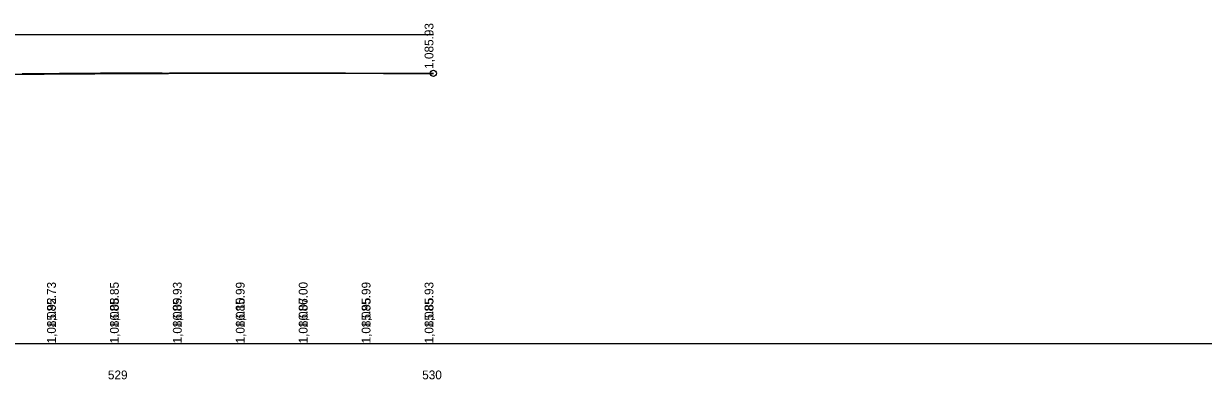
# Model space of a CAD drawing. Extents: x 2241514 to 2245530, y 509521 to 510188.
# Drawn here: x 2243146.9 to 2243521.9, y 509759.6 to 509872.8 of the extents above; entities that cross this region are included whole.
import ezdxf

# ---------------------------------------------------------------- set-up
doc = ezdxf.new("R2010")
doc.units = 0
for name, color, linetype in [('GK_Cells', 7, 'Continuous'), ('PF_P_Grade_Line', 7, 'Continuous'), ('PF_P_Sta_Elev_Text', 7, 'Continuous'), ('PF_P_Text', 7, 'Continuous'), ('PF_X_Ground_Line', 7, 'Continuous'), ('PF_X_Text', 7, 'Continuous')]:
    doc.layers.add(name, color=color, linetype=linetype)

msp = doc.modelspace()

# ---------------------------------------------------------------- linework, layer by layer
at = {"layer": 'GK_Cells'}
msp.add_line((2241529.6, 509771.03), (2245529.6, 509771.03), dxfattribs=at)
at = {"layer": 'PF_P_Grade_Line'}
msp.add_spline([(2242782.14, 509848.05), (2242792.04, 509848.44), (2242801.94, 509848.82), (2242811.84, 509849.19), (2242821.74, 509849.55), (2242831.64, 509849.9), (2242841.54, 509850.25), (2242851.44, 509850.58), (2242861.34, 509850.91), (2242871.24, 509851.23), (2242881.14, 509851.54), (2242891.04, 509851.84), (2242900.94, 509852.13), (2242910.84, 509852.42), (2242920.74, 509852.69), (2242930.64, 509852.96), (2242940.54, 509853.22), (2242950.44, 509853.47), (2242960.34, 509853.71), (2242970.24, 509853.95), (2242980.14, 509854.17), (2242990.04, 509854.39), (2242999.94, 509854.6), (2243009.84, 509854.8), (2243019.74, 509854.99), (2243029.64, 509855.17), (2243039.54, 509855.34), (2243049.44, 509855.51), (2243059.34, 509855.67), (2243069.24, 509855.82), (2243079.14, 509855.96), (2243089.04, 509856.09), (2243098.94, 509856.21), (2243108.84, 509856.32), (2243118.74, 509856.43), (2243128.64, 509856.53), (2243138.54, 509856.62), (2243148.44, 509856.7), (2243158.34, 509856.77), (2243168.24, 509856.83), (2243178.14, 509856.89), (2243188.04, 509856.93), (2243197.94, 509856.97), (2243207.84, 509857), (2243217.74, 509857.02), (2243227.64, 509857.03), (2243237.54, 509857.04), (2243247.44, 509857.03), (2243257.34, 509857.02), (2243267.24, 509857), (2243277.14, 509856.97)], degree=3, dxfattribs=at)
at = {"layer": 'PF_P_Text'}
msp.add_line((2242782.14, 509869.31), (2243277.14, 509869.31), dxfattribs=at)
msp.add_circle((2243277.14, 509856.97), 1, dxfattribs=at)
at = {"layer": 'PF_X_Ground_Line'}
for points in [[(2243146.43, 509856.9), (2243148.27, 509856.92), (2243148.65, 509856.92), (2243150.46, 509856.93), (2243151.49, 509856.93), (2243152.13, 509856.94), (2243152.81, 509856.94), (2243153.65, 509856.94), (2243154.83, 509856.94), (2243155.37, 509856.94), (2243155.95, 509856.94), (2243156.1, 509856.94), (2243157.34, 509856.95), (2243158.25, 509856.96), (2243158.58, 509856.96), (2243159.94, 509856.97), (2243161.41, 509856.98), (2243162.36, 509856.99), (2243163.99, 509857.01), (2243164.85, 509857.02), (2243165.15, 509857.02), (2243165.63, 509857.02), (2243167.05, 509857.04), (2243167.54, 509857.04), (2243168.51, 509857.05), (2243169.13, 509857.05), (2243169.71, 509857.05), (2243171.28, 509857.07), (2243171.32, 509857.07), (2243171.37, 509857.07), (2243172.45, 509857.09), (2243172.54, 509857.09), (2243173.47, 509857.1), (2243173.54, 509857.1), (2243175.21, 509857.11), (2243175.35, 509857.11), (2243175.62, 509857.11), (2243176.15, 509857.11), (2243178.14, 509857.11), (2243179.22, 509857.11), (2243180.12, 509857.11), (2243181.5, 509857.11), (2243181.99, 509857.1), (2243182.37, 509857.1), (2243184.3, 509857.1), (2243184.51, 509857.1), (2243186.28, 509857.09), (2243186.91, 509857.08), (2243188.11, 509857.07), (2243188.7, 509857.07), (2243190.42, 509857.06), (2243190.9, 509857.06), (2243192.04, 509857.05), (2243193.31, 509857.06), (2243194.99, 509857.08), (2243195.73, 509857.09), (2243196.18, 509857.1), (2243197.48, 509857.12), (2243198.57, 509857.14), (2243198.79, 509857.14), (2243200.26, 509857.14), (2243200.48, 509857.15), (2243200.89, 509857.14), (2243202.51, 509857.13), (2243203.03, 509857.12), (2243203.94, 509857.11), (2243205.73, 509857.09), (2243206.23, 509857.08), (2243208.41, 509857.07), (2243208.64, 509857.07), (2243208.73, 509857.06), (2243209.15, 509857.07), (2243209.49, 509857.07), (2243212.08, 509857.1), (2243213.06, 509857.11), (2243213.48, 509857.12), (2243213.83, 509857.12), (2243216.4, 509857.13), (2243216.95, 509857.13)], [(2243216.95, 509857.13), (2243217.97, 509857.13), (2243218.54, 509857.13), (2243219.58, 509857.13), (2243220.75, 509857.13), (2243222.08, 509857.12), (2243222.14, 509857.12), (2243222.34, 509857.12), (2243224.58, 509857.11), (2243225.04, 509857.1), (2243227.45, 509857.07), (2243227.49, 509857.07), (2243227.5, 509857.07), (2243229.88, 509857.07), (2243230.42, 509857.06), (2243230.74, 509857.07), (2243231.39, 509857.07), (2243232.78, 509857.07), (2243233.48, 509857.08), (2243234.75, 509857.09), (2243235.21, 509857.09), (2243236.18, 509857.1), (2243236.52, 509857.1), (2243237.25, 509857.11), (2243237.4, 509857.11), (2243237.96, 509857.11), (2243238.82, 509857.11), (2243239.12, 509857.11), (2243239.61, 509857.11), (2243240.88, 509857.1), (2243242.14, 509857.1), (2243243.27, 509857.1), (2243243.9, 509857.1), (2243244.43, 509857.09), (2243245.94, 509857.09), (2243247.78, 509857.08), (2243247.88, 509857.08), (2243248.13, 509857.08), (2243249.2, 509857.07), (2243251.81, 509857.03), (2243252.13, 509857.03), (2243252.27, 509857.03), (2243252.42, 509857.03), (2243254.12, 509857.02), (2243254.52, 509857.01), (2243254.77, 509857.01), (2243256.71, 509856.99), (2243257.93, 509856.97), (2243258.52, 509856.97), (2243261.27, 509856.95), (2243261.35, 509856.95), (2243263.38, 509856.94), (2243263.85, 509856.94), (2243265.4, 509856.93), (2243265.78, 509856.93), (2243266.46, 509856.93), (2243267.69, 509856.92), (2243267.81, 509856.92), (2243269.2, 509856.91), (2243269.25, 509856.91), (2243269.33, 509856.91), (2243272.54, 509856.9), (2243273.14, 509856.9), (2243274.44, 509856.9), (2243275.87, 509856.89), (2243275.96, 509856.89), (2243276.04, 509856.89), (2243277.14, 509856.89)]]:
    msp.add_lwpolyline(points, dxfattribs=at)

# ---------------------------------------------------------------- texts
at = {"layer": 'PF_P_Sta_Elev_Text'}
for s, p in [('529', (2243173.68, 509759.63)), ('530', (2243273.58, 509759.63))]:
    msp.add_text(s, height=2.8, dxfattribs=at).set_placement(p)
at = {"layer": 'PF_P_Text'}
for s, p in [('1,085.93', (2243277.14, 509858.37)), ('1,085.73', (2243157.14, 509776.03)), ('1,085.85', (2243177.14, 509776.03)), ('1,085.93', (2243197.14, 509776.03)), ('1,085.99', (2243217.14, 509776.03)), ('1,086.00', (2243237.14, 509776.03)), ('1,085.99', (2243257.14, 509776.03)), ('1,085.93', (2243277.14, 509776.03))]:
    msp.add_text(s, height=2.8, rotation=90, dxfattribs=at).set_placement(p)
at = {"layer": 'PF_X_Text'}
for s, p in [('1,085.92', (2243157.14, 509771.03)), ('1,086.08', (2243177.14, 509771.03)), ('1,086.09', (2243197.14, 509771.03)), ('1,086.10', (2243217.14, 509771.03)), ('1,086.07', (2243237.14, 509771.03)), ('1,085.95', (2243257.14, 509771.03)), ('1,085.85', (2243277.14, 509771.03))]:
    msp.add_text(s, height=2.8, rotation=90, dxfattribs=at).set_placement(p)

doc.saveas('drawing.dxf')
